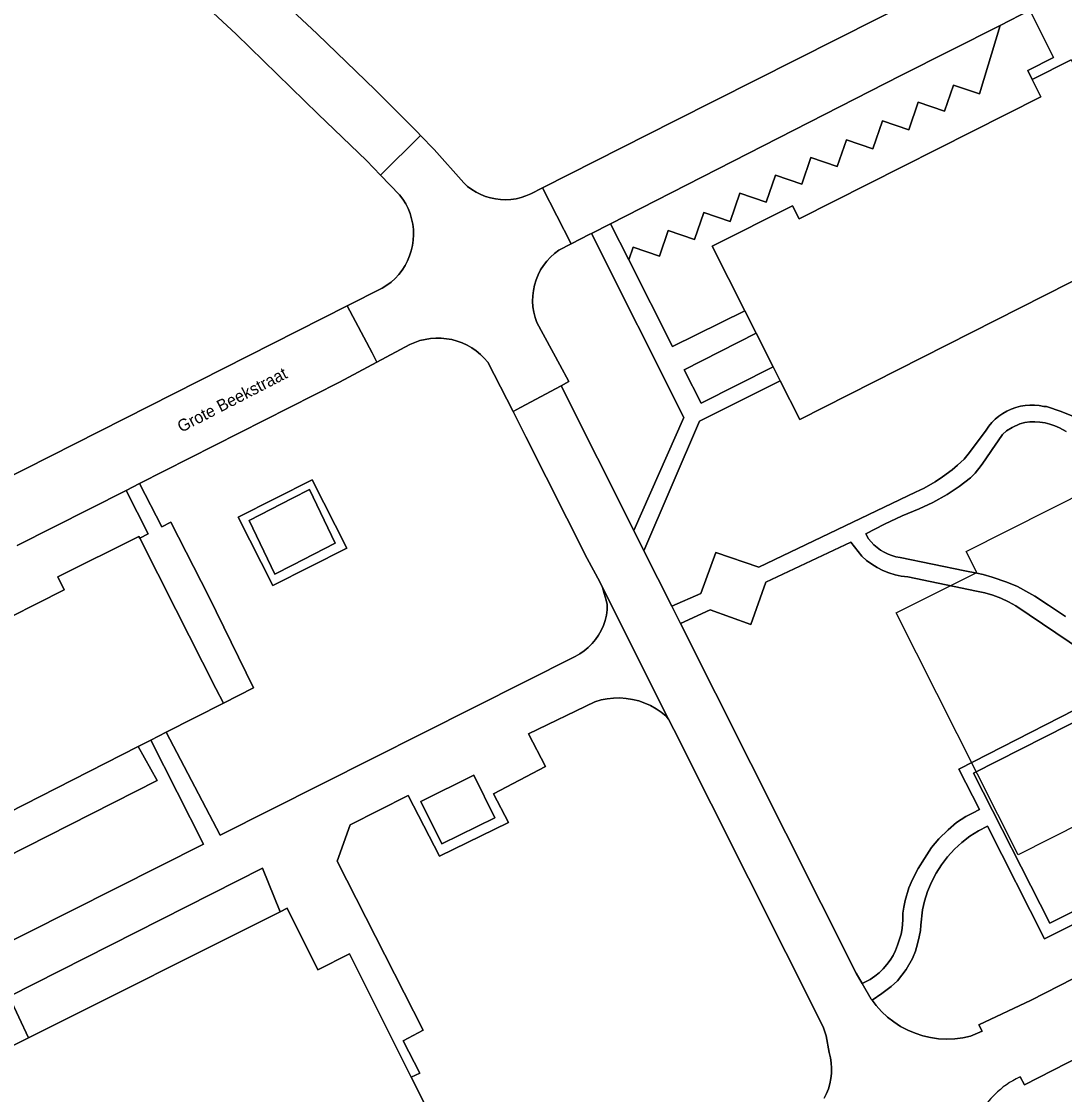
# Model space of a CAD drawing. Extents: x 158132 to 159664, y 385256 to 387218.
# Drawn here: x 158977.3 to 159064.7, y 386327.7 to 386417.6 of the extents above; entities that cross this region are included whole.
import ezdxf

# ---------------------------------------------------------------- set-up
doc = ezdxf.new("R2010")
doc.units = 0
for name, color, linetype in [('IMGEO_Groenvoorziening', 7, 'Continuous'), ('IMGEO_Openbare_ruimte_label', 7, 'Continuous'), ('IMGEO_Pand', 7, 'Continuous'), ('IMGEO_Pand_vergunning_verleend', 7, 'Continuous'), ('IMGEO_Parkeervlak_open', 7, 'Continuous'), ('IMGEO_Rijbaan_lokaal_gesloten', 7, 'Continuous'), ('IMGEO_Rijbaan_lokaal_open', 7, 'Continuous'), ('IMGEO_Terreindeel_gesloten', 7, 'Continuous'), ('IMGEO_Voetpad_open', 7, 'Continuous')]:
    doc.layers.add(name, color=color, linetype=linetype)

msp = doc.modelspace()

# ---------------------------------------------------------------- linework, layer by layer
at = {"layer": 'IMGEO_Groenvoorziening'}
for points in [[(158994.381, 386423.734), (159002.053, 386416.539), (159006.958, 386411.812), (159010.488, 386408.269), (159010.711, 386408.038), (159011.861, 386406.847), (159014.34, 386404.05), (159014.662, 386403.761), (159015.009, 386403.502), (159015.376, 386403.274), (159015.762, 386403.079), (159016.164, 386402.919), (159016.578, 386402.794), (159017.002, 386402.707), (159017.431, 386402.656), (159017.864, 386402.644), (159018.295, 386402.669), (159018.723, 386402.733), (159019.144, 386402.833), (159019.554, 386402.97), (159019.951, 386403.143), (159020.934, 386403.641), (159032.021, 386409.258), (159052.355, 386419.514)], [(158971.379, 386376.952), (159004.587, 386393.751), (159007.52, 386395.235), (159007.902, 386395.477), (159008.261, 386395.752), (159008.595, 386396.056), (159008.902, 386396.388), (159009.179, 386396.745), (159009.424, 386397.125), (159009.635, 386397.525), (159009.811, 386397.941), (159009.951, 386398.371), (159010.052, 386398.812), (159010.116, 386399.259), (159010.14, 386399.711), (159010.126, 386400.162), (159010.072, 386400.611), (159009.98, 386401.054), (159009.85, 386401.487), (159009.684, 386401.907), (159009.481, 386402.311), (159009.245, 386402.696), (159008.976, 386403.059), (159007.376, 386404.702), (159006.193, 386405.917), (159002.147, 386409.818), (158995.269, 386416.498), (158989.531, 386421.872)], [(159067.126, 386396.707), (159042.483, 386384.25), (159040.849, 386387.477), (159034.097, 386384.094), (159029.432, 386373.255), (159031.762, 386368.614), (159034.203, 386369.659), (159035.452, 386373.101), (159039.065, 386371.881), (159052.189, 386378.145), (159052.915, 386378.503), (159053.824, 386379.012), (159054.452, 386379.434), (159055.263, 386380.034), (159055.704, 386380.417), (159056.247, 386380.925), (159056.712, 386381.476), (159058.097, 386383.36), (159058.325, 386383.685), (159058.581, 386383.989), (159058.863, 386384.27), (159059.168, 386384.524), (159059.495, 386384.751), (159059.84, 386384.948), (159060.201, 386385.115), (159060.576, 386385.248), (159060.96, 386385.349), (159061.352, 386385.415), (159061.749, 386385.446), (159062.146, 386385.443), (159062.542, 386385.404), (159062.933, 386385.331), (159063.138, 386385.316), (159064.386, 386384.922), (159066.099, 386384.214)], [(159064.788, 386383.247), (159064.227, 386383.532), (159063.841, 386383.71), (159063.439, 386383.851), (159063.027, 386383.954), (159062.606, 386384.019), (159062.182, 386384.045), (159061.757, 386384.032), (159061.334, 386383.98), (159060.919, 386383.888), (159060.284, 386383.574), (159059.789, 386383.3), (159059.47, 386382.976), (159059.093, 386382.448), (159058.603, 386381.727), (159058, 386380.851), (159057.666, 386380.38), (159057.173, 386379.757), (159056.776, 386379.351), (159055.847, 386378.643), (159054.821, 386377.961), (159053.644, 386377.286), (159052.477, 386376.761), (159051.068, 386376.172), (159049.591, 386375.486), (159048.022, 386374.653), (159048.232, 386374.259), (159048.456, 386373.988), (159048.703, 386373.737), (159048.971, 386373.508), (159049.257, 386373.303), (159049.56, 386373.124), (159049.877, 386372.972), (159050.206, 386372.848), (159050.545, 386372.753), (159050.891, 386372.687), (159056.308, 386371.578), (159057.316, 386371.382), (159057.859, 386371.25), (159058.59, 386371.037), (159059.829, 386370.62), (159060.718, 386370.246), (159061.668, 386369.736), (159062.162, 386369.446), (159063.326, 386368.695), (159064.752, 386367.755)], [(158960.66, 386359.768), (158980.888, 386369.986), (158980.351, 386371.073), (158987.123, 386374.454), (158987.201, 386374.3), (158987.911, 386374.663), (158986.063, 386378.306), (158976.954, 386373.684)], [(159067.295, 386364.116), (159060.592, 386368.622), (159059.976, 386368.977), (159059.333, 386369.281), (159058.669, 386369.532), (159057.986, 386369.73), (159057.29, 386369.873), (159051.526, 386371.059), (159050.992, 386371.128), (159050.466, 386371.241), (159049.951, 386371.399), (159049.451, 386371.6), (159048.971, 386371.843), (159048.512, 386372.125), (159048.08, 386372.446), (159047.676, 386372.802), (159046.754, 386373.98), (159039.657, 386370.617), (159038.401, 386367.08), (159034.993, 386368.305), (159032.499, 386367.147), (159047.2, 386337.866), (159047.709, 386337.005), (159048.392, 386337.354), (159048.776, 386337.617), (159049.136, 386337.911), (159049.471, 386338.235), (159049.777, 386338.586), (159050.053, 386338.961), (159050.296, 386339.357), (159050.505, 386339.773), (159050.678, 386340.205), (159050.815, 386340.65), (159050.976, 386341.127), (159051.066, 386341.627), (159051.107, 386342.335), (159051.119, 386342.889), (159051.19, 386343.39), (159051.301, 386343.948), (159051.618, 386345.02), (159051.926, 386345.706), (159052.41, 386346.631), (159052.931, 386347.468), (159053.527, 386348.392), (159054.143, 386349.123), (159054.909, 386349.89), (159055.617, 386350.481), (159056.381, 386350.988), (159056.95, 386351.26), (159057.547, 386351.569), (159055.815, 386354.967), (159069.132, 386361.769)], [(159044.539, 386327.391), (159044.734, 386327.784), (159044.893, 386328.193), (159045.015, 386328.615), (159045.1, 386329.045), (159045.146, 386329.482), (159045.154, 386329.921), (159045.123, 386330.359), (159045.053, 386330.792), (159044.945, 386331.217), (159044.696, 386332.625), (159044.44, 386333.382), (159031.934, 386358.269), (159031.501, 386359.154), (159031.304, 386359.391), (159030.891, 386359.726), (159030.45, 386360.023), (159029.984, 386360.281), (159029.498, 386360.498), (159028.995, 386360.671), (159028.479, 386360.8), (159027.953, 386360.883), (159027.423, 386360.92), (159026.891, 386360.91), (159026.362, 386360.855), (159025.839, 386360.753), (159025.328, 386360.606), (159019.756, 386357.903), (159021.197, 386355.179), (159016.841, 386352.9), (159018.099, 386350.481), (159012.319, 386347.664), (159009.697, 386352.759), (159004.834, 386350.295), (159003.745, 386347.246), (159010.944, 386333.095), (159009.257, 386332.21), (159010.654, 386329.506), (159009.946, 386329.152), (159011.327, 386326.394)], [(159077.738, 386348.161), (159062.977, 386340.742), (159058.202, 386350.173), (159057.451, 386349.785), (159056.737, 386349.332), (159056.065, 386348.818), (159055.442, 386348.247), (159054.871, 386347.624), (159054.357, 386346.952), (159053.904, 386346.238), (159053.515, 386345.487), (159053.194, 386344.705), (159052.943, 386343.898), (159052.756, 386343.169), (159052.627, 386341.889), (159052.602, 386341.434), (159052.499, 386340.921), (159052.333, 386340.33), (159052.192, 386339.726), (159051.94, 386339.108), (159051.405, 386338.167), (159050.683, 386337.227), (159050.137, 386336.764), (159049.35, 386336.174), (159048.542, 386335.617), (159048.883, 386335.163), (159049.335, 386334.66), (159049.828, 386334.199), (159050.36, 386333.783), (159050.927, 386333.415), (159051.523, 386333.098), (159052.145, 386332.834), (159052.787, 386332.626), (159053.446, 386332.474), (159054.115, 386332.381), (159054.789, 386332.347), (159055.464, 386332.371), (159056.135, 386332.455), (159056.795, 386332.597), (159057.754, 386333.009), (159057.491, 386333.552), (159061.863, 386335.619), (159079.47, 386344.616)], [(159070.847, 386333.393), (159061.295, 386328.518), (159060.937, 386329.18), (159060.892, 386329.157)]]:
    msp.add_lwpolyline(points, dxfattribs=at)
for points in [[(159062.667, 386411.268), (159061.956, 386412.719), (159061.576, 386413.48), (159063.739, 386414.56), (159061.767, 386418.511), (159059.264, 386417.248), (159057.53, 386411.501), (159055.362, 386412.243), (159055.357, 386412.23), (159054.616, 386410.062), (159052.408, 386410.817), (159051.616, 386408.503), (159049.408, 386409.258), (159048.605, 386406.911), (159046.397, 386407.667), (159045.63, 386405.425), (159043.422, 386406.18), (159042.656, 386403.942), (159040.448, 386404.697), (159039.675, 386402.435), (159037.467, 386403.191), (159036.656, 386400.82), (159034.448, 386401.576), (159033.677, 386399.321), (159031.468, 386400.076), (159030.729, 386397.916), (159028.521, 386398.671), (159028.159, 386397.612), (159031.84, 386390.365), (159037.884, 386393.336), (159035.144, 386398.748), (159041.883, 386402.146), (159042.432, 386401.057)], [(159025.047, 386399.819), (159024.909, 386399.748), (159023.352, 386398.959), (159022.31, 386398.432), (159021.946, 386398.156), (159021.608, 386397.849), (159021.299, 386397.513), (159021.021, 386397.15), (159020.777, 386396.764), (159020.569, 386396.358), (159020.398, 386395.934), (159020.267, 386395.497), (159020.174, 386395.05), (159020.123, 386394.596), (159020.112, 386394.139), (159020.143, 386393.684), (159020.214, 386393.233), (159020.325, 386392.79), (159020.476, 386392.359), (159022.4, 386388.82), (159023.135, 386387.414), (159022.496, 386387.07), (159028.588, 386374.936), (159032.789, 386384.395)], [(159040.251, 386388.659), (159038.833, 386391.46), (159032.804, 386388.403), (159034.228, 386385.62)], [(159024.694, 386372.603), (159019.552, 386382.797), (159018.47, 386384.905), (159016.351, 386389.036), (159016.056, 386389.378), (159015.734, 386389.694), (159015.386, 386389.982), (159015.015, 386390.239), (159014.623, 386390.464), (159014.214, 386390.654), (159013.79, 386390.809), (159013.354, 386390.928), (159012.91, 386391.009), (159012.461, 386391.052), (159012.01, 386391.057), (159011.559, 386391.024), (159011.114, 386390.952), (159010.675, 386390.843), (159010.248, 386390.698), (159009.835, 386390.516), (159007.069, 386389.043), (159003.946, 386387.379), (158987.197, 386378.881), (158989.061, 386375.251), (158989.8, 386375.631), (158992.995, 386369.409), (158996.721, 386361.766), (158994.21, 386360.489), (158989.434, 386358.059), (158993.94, 386349.441), (159023.663, 386364.383), (159024.055, 386364.605), (159024.425, 386364.861), (159024.771, 386365.149), (159025.089, 386365.468), (159025.377, 386365.814), (159025.632, 386366.184), (159025.853, 386366.576), (159026.038, 386366.987), (159026.185, 386367.412), (159026.293, 386367.849), (159026.36, 386368.294), (159026.362, 386368.745), (159026.283, 386369.11), (159026.11, 386369.676), (159025.974, 386370.166), (159025.734, 386370.656)], [(159004.544, 386373.455), (158998.35, 386370.326), (158995.456, 386376.053), (159001.651, 386379.182)], [(158988.138, 386357.399), (158987.079, 386356.86), (158988.658, 386354.016), (158972.191, 386345.65), (158970.675, 386348.513), (158969.767, 386348.051), (158974.066, 386339.37), (158992.552, 386348.687)], [(158998.976, 386343.02), (158997.487, 386346.666), (158976.26, 386335.915), (158977.889, 386332.461)]]:
    msp.add_lwpolyline(points, close=True, dxfattribs=at)
for centre, radius, start, end in [((159063.76, 386322.839), 6.938, 114.41851, 135.4357), ((159063.241, 386322.951), 6.496, 132.92122, 197.984)]:
    msp.add_arc(centre, radius, start, end, dxfattribs=at)
at = {"layer": 'IMGEO_Pand'}
for points in [[(159065.214, 386414.362), (159061.956, 386412.719), (159062.667, 386411.268), (159042.432, 386401.057), (159041.883, 386402.146), (159035.144, 386398.748), (159037.884, 386393.336), (159038.833, 386391.46), (159040.251, 386388.659), (159040.849, 386387.477), (159042.483, 386384.25), (159067.126, 386396.707)], [(158970.675, 386348.513), (158987.079, 386356.86), (158988.138, 386357.399), (158989.434, 386358.059), (158994.21, 386360.489), (158993.592, 386361.707), (158990.238, 386368.316), (158987.201, 386374.3), (158987.123, 386374.454), (158980.351, 386371.073), (158980.888, 386369.986), (158960.66, 386359.768)], [(158975.642, 386315.413), (158977.782, 386316.434), (158980.533, 386310.94), (159005.285, 386323.334), (159004.869, 386324.163), (159010.401, 386326.933), (159010.802, 386326.131), (159011.034, 386326.247), (159011.327, 386326.394), (159009.946, 386329.152), (159004.774, 386339.482), (159002.125, 386338.155), (158999.546, 386343.305), (158998.976, 386343.02), (158977.889, 386332.461), (158975.292, 386331.161)]]:
    msp.add_lwpolyline(points, dxfattribs=at)
for points in [[(158998.534, 386371.285), (159000, 386372.041), (159003.582, 386373.888), (159001.425, 386378.382), (159000, 386377.647), (158996.377, 386375.779)], [(159016.953, 386350.894), (159015.182, 386354.466), (159010.74, 386352.263), (159012.512, 386348.691)]]:
    msp.add_lwpolyline(points, close=True, dxfattribs=at)
at = {"layer": 'IMGEO_Pand_vergunning_verleend'}
msp.add_lwpolyline([(159050.566, 386368.036), (159057.316, 386371.439), (159056.434, 386373.19), (159088.099, 386389.152), (159085.805, 386393.704), (159116.592, 386409.224), (159123.517, 386395.487), (159125.076, 386396.273), (159128.071, 386390.332), (159124.613, 386388.589), (159130.927, 386376.065), (159110.742, 386365.89), (159098.147, 386390.876), (159089.73, 386386.633), (159092.108, 386381.915), (159085.183, 386378.425), (159091.591, 386365.714), (159079.324, 386359.397), (159081.204, 386355.823), (159075.094, 386353.069), (159074.314, 386354.616), (159060.772, 386347.79)], close=True, dxfattribs=at)
at = {"layer": 'IMGEO_Parkeervlak_open'}
msp.add_lwpolyline([(159059.264, 386417.248), (159050.937, 386413.048), (159026.628, 386400.627), (159028.159, 386397.612), (159028.521, 386398.671), (159030.729, 386397.916), (159031.468, 386400.076), (159033.677, 386399.321), (159034.448, 386401.576), (159036.656, 386400.82), (159037.467, 386403.191), (159039.675, 386402.435), (159040.448, 386404.697), (159042.656, 386403.942), (159043.422, 386406.18), (159045.63, 386405.425), (159046.397, 386407.667), (159048.605, 386406.911), (159049.408, 386409.258), (159051.616, 386408.503), (159052.408, 386410.817), (159054.616, 386410.062), (159055.357, 386412.23), (159055.362, 386412.243), (159057.53, 386411.501)], close=True, dxfattribs=at)
at = {"layer": 'IMGEO_Rijbaan_lokaal_gesloten'}
for points in [[(158976.954, 386373.684), (158986.063, 386378.306), (158987.197, 386378.881), (159003.946, 386387.379), (159007.069, 386389.043), (159006.663, 386389.814), (159004.587, 386393.751), (158971.379, 386376.952)], [(159079.47, 386344.616), (159061.863, 386335.619), (159057.491, 386333.552), (159057.754, 386333.009), (159056.795, 386332.597), (159056.135, 386332.455), (159055.464, 386332.371), (159054.789, 386332.347), (159054.115, 386332.381), (159053.446, 386332.474), (159052.787, 386332.626), (159052.145, 386332.834), (159051.523, 386333.098), (159050.927, 386333.415), (159050.36, 386333.783), (159049.828, 386334.199), (159049.335, 386334.66), (159048.883, 386335.163), (159048.542, 386335.617), (159048.477, 386335.703), (159047.709, 386337.005), (159047.2, 386337.866), (159032.499, 386367.147), (159031.762, 386368.614), (159029.432, 386373.255), (159028.588, 386374.936), (159022.496, 386387.07), (159019.092, 386385.239), (159018.47, 386384.905), (159019.552, 386382.797), (159024.694, 386372.603), (159025.734, 386370.656), (159025.974, 386370.166), (159031.501, 386359.154), (159031.934, 386358.269), (159044.44, 386333.382), (159044.696, 386332.625), (159044.945, 386331.217), (159045.053, 386330.792), (159045.123, 386330.359), (159045.154, 386329.921), (159045.146, 386329.482), (159045.1, 386329.045), (159045.015, 386328.615), (159044.893, 386328.193), (159044.734, 386327.784), (159044.539, 386327.391)], [(159060.892, 386329.157), (159060.937, 386329.18), (159061.295, 386328.518), (159070.847, 386333.393), (159072.465, 386334.219), (159085.768, 386341.008), (159090.616, 386343.54), (159115.248, 386356.119), (159131.574, 386364.295), (159131.513, 386364.412), (159131.347, 386364.73), (159133.011, 386365.593)]]:
    msp.add_lwpolyline(points, dxfattribs=at)
for centre, radius, start, end in [((159063.76, 386322.839), 6.938, 114.41851, 135.4357), ((159063.241, 386322.951), 6.496, 132.92122, 197.984)]:
    msp.add_arc(centre, radius, start, end, dxfattribs=at)
at = {"layer": 'IMGEO_Rijbaan_lokaal_open'}
for points in [[(159076.553, 386431.686), (159057.352, 386422.057), (159052.355, 386419.514), (159032.021, 386409.258), (159020.934, 386403.641), (159023.352, 386398.959), (159024.909, 386399.748), (159025.047, 386399.819), (159026.628, 386400.627), (159050.937, 386413.048), (159059.264, 386417.248), (159061.767, 386418.511), (159078.042, 386426.722)], [(158989.531, 386421.872), (158995.269, 386416.498), (159002.147, 386409.818), (159006.193, 386405.917), (159007.376, 386404.702), (159010.711, 386408.038), (159010.488, 386408.269), (159006.958, 386411.812), (159002.053, 386416.539), (158994.381, 386423.734)]]:
    msp.add_lwpolyline(points, dxfattribs=at)
msp.add_lwpolyline([(159020.777, 386396.764), (159021.021, 386397.15), (159021.299, 386397.513), (159021.608, 386397.849), (159021.946, 386398.156), (159022.31, 386398.432), (159023.352, 386398.959), (159020.934, 386403.641), (159019.951, 386403.143), (159019.554, 386402.97), (159019.144, 386402.833), (159018.723, 386402.733), (159018.295, 386402.669), (159017.864, 386402.644), (159017.431, 386402.656), (159017.002, 386402.707), (159016.578, 386402.794), (159016.164, 386402.919), (159015.762, 386403.079), (159015.376, 386403.274), (159015.009, 386403.502), (159014.662, 386403.761), (159014.34, 386404.05), (159011.861, 386406.847), (159010.711, 386408.038), (159007.376, 386404.702), (159008.976, 386403.059), (159009.245, 386402.696), (159009.481, 386402.311), (159009.684, 386401.907), (159009.85, 386401.487), (159009.98, 386401.054), (159010.072, 386400.611), (159010.126, 386400.162), (159010.14, 386399.711), (159010.116, 386399.259), (159010.052, 386398.812), (159009.951, 386398.371), (159009.811, 386397.941), (159009.635, 386397.525), (159009.424, 386397.125), (159009.179, 386396.745), (159008.902, 386396.388), (159008.595, 386396.056), (159008.261, 386395.752), (159007.902, 386395.477), (159007.52, 386395.235), (159004.587, 386393.751), (159006.663, 386389.814), (159007.069, 386389.043), (159009.835, 386390.516), (159010.248, 386390.698), (159010.675, 386390.843), (159011.114, 386390.952), (159011.559, 386391.024), (159012.01, 386391.057), (159012.461, 386391.052), (159012.91, 386391.009), (159013.354, 386390.928), (159013.79, 386390.809), (159014.214, 386390.654), (159014.623, 386390.464), (159015.015, 386390.239), (159015.386, 386389.982), (159015.734, 386389.694), (159016.056, 386389.378), (159016.351, 386389.036), (159018.47, 386384.905), (159019.092, 386385.239), (159022.496, 386387.07), (159023.135, 386387.414), (159022.4, 386388.82), (159020.476, 386392.359), (159020.325, 386392.79), (159020.214, 386393.233), (159020.143, 386393.684), (159020.112, 386394.139), (159020.123, 386394.596), (159020.174, 386395.05), (159020.267, 386395.497), (159020.398, 386395.934), (159020.569, 386396.358)], close=True, dxfattribs=at)
at = {"layer": 'IMGEO_Terreindeel_gesloten'}
msp.add_lwpolyline([(159057.023, 386354.632), (159063.424, 386342.05), (159087.338, 386354.081), (159080.924, 386366.724)], close=True, dxfattribs=at)
at = {"layer": 'IMGEO_Voetpad_open'}
for points in [[(159079.2, 386421.422), (159077.37, 386425.356), (159078.042, 386426.722), (159061.767, 386418.511), (159063.739, 386414.56), (159061.576, 386413.48), (159061.956, 386412.719), (159065.214, 386414.362), (159066.142, 386412.523), (159080.11, 386419.579)], [(159034.097, 386384.094), (159040.849, 386387.477), (159040.251, 386388.659), (159034.228, 386385.62), (159032.804, 386388.403), (159038.833, 386391.46), (159037.884, 386393.336), (159031.84, 386390.365), (159028.159, 386397.612), (159026.628, 386400.627), (159025.047, 386399.819), (159032.789, 386384.395), (159028.588, 386374.936), (159029.432, 386373.255)], [(158987.197, 386378.881), (158986.063, 386378.306), (158987.911, 386374.663), (158987.201, 386374.3), (158990.238, 386368.316), (158993.592, 386361.707), (158994.21, 386360.489), (158996.721, 386361.766), (158992.995, 386369.409), (158989.8, 386375.631), (158989.061, 386375.251)], [(159004.544, 386373.455), (159001.651, 386379.182), (158995.456, 386376.053), (158998.35, 386370.326)], [(158998.534, 386371.285), (158996.377, 386375.779), (159000, 386377.647), (159001.425, 386378.382), (159003.582, 386373.888), (159000, 386372.041)], [(159057.023, 386354.632), (159080.924, 386366.724), (159087.338, 386354.081), (159063.424, 386342.05)], [(158987.079, 386356.86), (158970.675, 386348.513), (158972.191, 386345.65), (158988.658, 386354.016)], [(159016.953, 386350.894), (159012.512, 386348.691), (159010.74, 386352.263), (159015.182, 386354.466)]]:
    msp.add_lwpolyline(points, close=True, dxfattribs=at)
for points in [[(159066.099, 386384.214), (159064.386, 386384.922), (159063.138, 386385.316), (159062.933, 386385.331), (159062.542, 386385.404), (159062.146, 386385.443), (159061.749, 386385.446), (159061.352, 386385.415), (159060.96, 386385.349), (159060.576, 386385.248), (159060.201, 386385.115), (159059.84, 386384.948), (159059.495, 386384.751), (159059.168, 386384.524), (159058.863, 386384.27), (159058.581, 386383.989), (159058.325, 386383.685), (159058.097, 386383.36), (159056.712, 386381.476), (159056.247, 386380.925), (159055.704, 386380.417), (159055.263, 386380.034), (159054.452, 386379.434), (159053.824, 386379.012), (159052.915, 386378.503), (159052.189, 386378.145), (159039.065, 386371.881), (159035.452, 386373.101), (159034.203, 386369.659), (159031.762, 386368.614), (159032.499, 386367.147), (159034.993, 386368.305), (159038.401, 386367.08), (159039.657, 386370.617), (159046.754, 386373.98), (159047.676, 386372.802), (159048.08, 386372.446), (159048.512, 386372.125), (159048.971, 386371.843), (159049.451, 386371.6), (159049.951, 386371.399), (159050.466, 386371.241), (159050.992, 386371.128), (159051.526, 386371.059), (159057.29, 386369.873), (159057.986, 386369.73), (159058.669, 386369.532), (159059.333, 386369.281), (159059.976, 386368.977), (159060.592, 386368.622), (159067.295, 386364.116)], [(159064.752, 386367.755), (159063.326, 386368.695), (159062.162, 386369.446), (159061.668, 386369.736), (159060.718, 386370.246), (159059.829, 386370.62), (159058.59, 386371.037), (159057.859, 386371.25), (159057.316, 386371.382), (159056.308, 386371.578), (159050.891, 386372.687), (159050.545, 386372.753), (159050.206, 386372.848), (159049.877, 386372.972), (159049.56, 386373.124), (159049.257, 386373.303), (159048.971, 386373.508), (159048.703, 386373.737), (159048.456, 386373.988), (159048.232, 386374.259), (159048.022, 386374.653), (159049.591, 386375.486), (159051.068, 386376.172), (159052.477, 386376.761), (159053.644, 386377.286), (159054.821, 386377.961), (159055.847, 386378.643), (159056.776, 386379.351), (159057.173, 386379.757), (159057.666, 386380.38), (159058, 386380.851), (159058.603, 386381.727), (159059.093, 386382.448), (159059.47, 386382.976), (159059.789, 386383.3), (159060.284, 386383.574), (159060.919, 386383.888), (159061.334, 386383.98), (159061.757, 386384.032), (159062.182, 386384.045), (159062.606, 386384.019), (159063.027, 386383.954), (159063.439, 386383.851), (159063.841, 386383.71), (159064.227, 386383.532), (159064.788, 386383.247)], [(158975.292, 386331.161), (158977.889, 386332.461), (158976.26, 386335.915), (158997.487, 386346.666), (158998.976, 386343.02), (158999.546, 386343.305), (159002.125, 386338.155), (159004.774, 386339.482), (159009.946, 386329.152), (159010.654, 386329.506), (159009.257, 386332.21), (159010.944, 386333.095), (159003.745, 386347.246), (159004.834, 386350.295), (159009.697, 386352.759), (159012.319, 386347.664), (159018.099, 386350.481), (159016.841, 386352.9), (159021.197, 386355.179), (159019.756, 386357.903), (159025.328, 386360.606), (159025.839, 386360.753), (159026.362, 386360.855), (159026.891, 386360.91), (159027.423, 386360.92), (159027.953, 386360.883), (159028.479, 386360.8), (159028.995, 386360.671), (159029.498, 386360.498), (159029.984, 386360.281), (159030.45, 386360.023), (159030.891, 386359.726), (159031.304, 386359.391), (159031.501, 386359.154), (159025.974, 386370.166), (159026.11, 386369.676), (159026.283, 386369.11), (159026.362, 386368.745), (159026.36, 386368.294), (159026.293, 386367.849), (159026.185, 386367.412), (159026.038, 386366.987), (159025.853, 386366.576), (159025.632, 386366.184), (159025.377, 386365.814), (159025.089, 386365.468), (159024.771, 386365.149), (159024.425, 386364.861), (159024.055, 386364.605), (159023.663, 386364.383), (158993.94, 386349.441), (158989.434, 386358.059), (158988.138, 386357.399), (158992.552, 386348.687), (158974.066, 386339.37)], [(159069.132, 386361.769), (159055.815, 386354.967), (159057.547, 386351.569), (159056.95, 386351.26), (159056.381, 386350.988), (159055.617, 386350.481), (159054.909, 386349.89), (159054.143, 386349.123), (159053.527, 386348.392), (159052.931, 386347.468), (159052.41, 386346.631), (159051.926, 386345.706), (159051.618, 386345.02), (159051.301, 386343.948), (159051.19, 386343.39), (159051.119, 386342.889), (159051.107, 386342.335), (159051.066, 386341.627), (159050.976, 386341.127), (159050.815, 386340.65), (159050.678, 386340.205), (159050.505, 386339.773), (159050.296, 386339.357), (159050.053, 386338.961), (159049.777, 386338.586), (159049.471, 386338.235), (159049.136, 386337.911), (159048.776, 386337.617), (159048.392, 386337.354), (159047.709, 386337.005), (159048.477, 386335.703), (159048.542, 386335.617), (159049.35, 386336.174), (159050.137, 386336.764), (159050.683, 386337.227), (159051.405, 386338.167), (159051.94, 386339.108), (159052.192, 386339.726), (159052.333, 386340.33), (159052.499, 386340.921), (159052.602, 386341.434), (159052.627, 386341.889), (159052.756, 386343.169), (159052.943, 386343.898), (159053.194, 386344.705), (159053.515, 386345.487), (159053.904, 386346.238), (159054.357, 386346.952), (159054.871, 386347.624), (159055.442, 386348.247), (159056.065, 386348.818), (159056.737, 386349.332), (159057.451, 386349.785), (159058.202, 386350.173), (159062.977, 386340.742), (159077.738, 386348.161)]]:
    msp.add_lwpolyline(points, dxfattribs=at)

# ---------------------------------------------------------------- texts
at = {"layer": 'IMGEO_Openbare_ruimte_label'}
msp.add_text('Grote Beekstraat', height=1, rotation=27.33408, dxfattribs=at).set_placement((158990.684, 386383.125))

doc.saveas('drawing.dxf')
